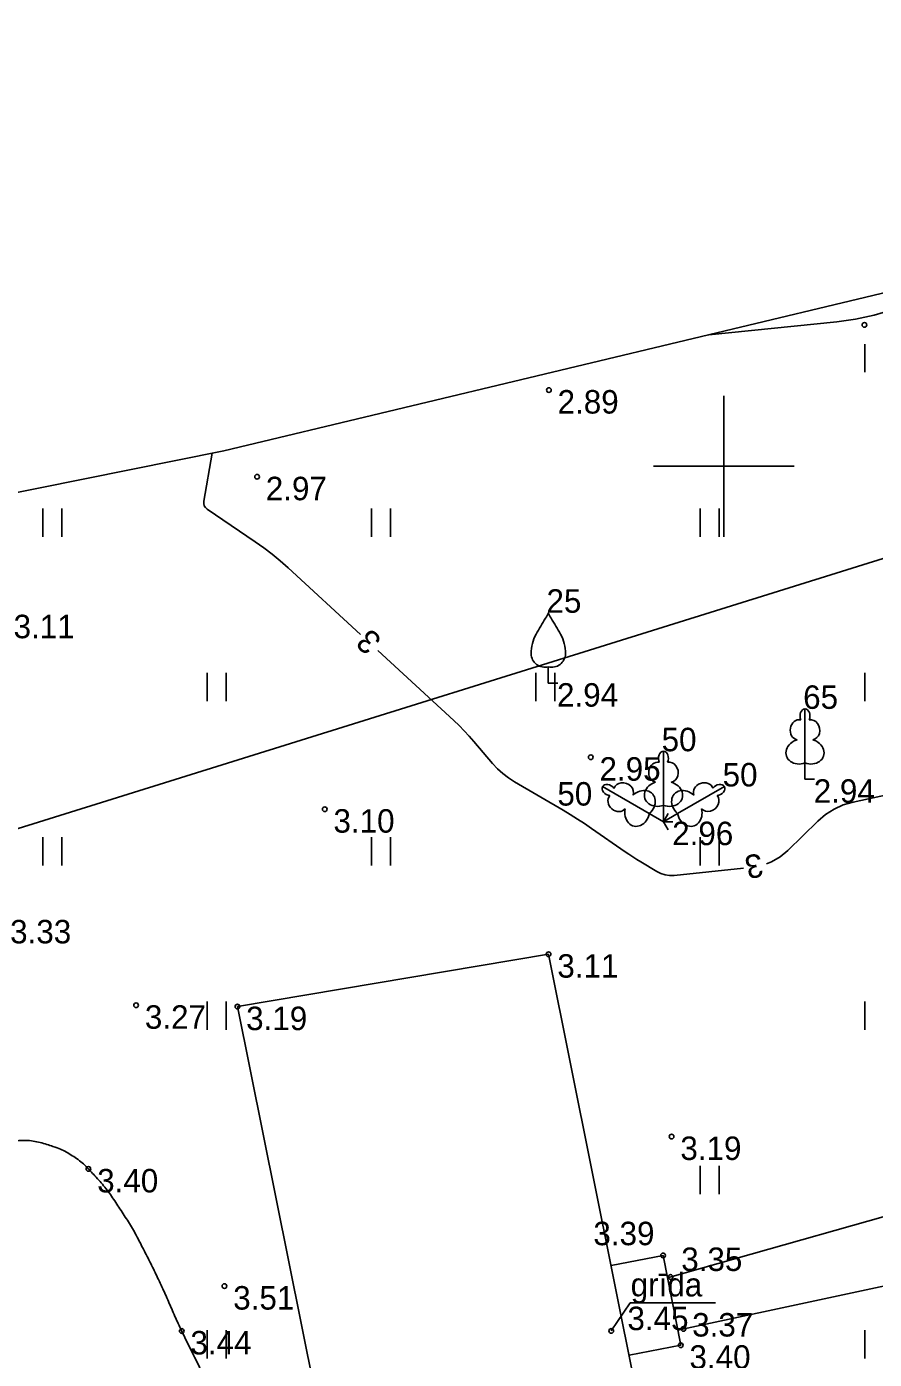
# Model space of a CAD drawing. Extents: x 321079 to 321220, y 257030 to 257220.
# Drawn here: x 321135.15 to 321153.21, y 257130.98 to 257159.36 of the extents above; entities that cross this region are included whole.
import ezdxf

# ---------------------------------------------------------------- set-up
doc = ezdxf.new("R2010")
doc.units = 0
for name, color, linetype in [('BUVE_BDET_####_####_#', 7, 'Continuous'), ('BUVE_BDET_####_TKST_#', 7, 'Continuous'), ('BUVE_EKAS_####_####_#', 7, 'Continuous'), ('CELI_CMAL_####_####_#', 7, 'Continuous'), ('GEOD_ELEM_####_####_#', 7, 'Continuous'), ('RAMI_UZMR_####_####_#', 7, 'Continuous'), ('RELJ_AATZ_####_TKST_#', 7, 'Continuous'), ('RELJ_ELEM_####_####_#', 7, 'Continuous'), ('RELJ_HORZ_####_TKST_#', 7, 'Continuous'), ('RELJ_HORZ_PAMT_####_#', 7, 'Continuous'), ('RELJ_HORZ_PUSH_####_#', 7, 'Continuous'), ('ROBZ_UZMR_####_####_#', 7, 'Continuous'), ('TERT_DIAM_####_TKST_#', 7, 'Continuous'), ('TERT_ELEM_####_####_#', 7, 'Continuous'), ('TERT_KONT_####_####_#', 7, 'Continuous')]:
    doc.layers.add(name, color=color, linetype=linetype)

msp = doc.modelspace()

# ---------------------------------------------------------------- linework, layer by layer
at = {"layer": 'BUVE_BDET_####_####_#'}
for points in [[(321147.601, 257132.975), (321148.708, 257133.192), (321149.083, 257131.28), (321147.985, 257131.065)], [(321147.604, 257131.586), (321148.008, 257132.186), (321149.825, 257132.186)]]:
    msp.add_lwpolyline(points, dxfattribs=at)
at = {"layer": 'BUVE_EKAS_####_####_#'}
for p, q in [((321146.269, 257139.608), (321139.642, 257138.491)), ((321150.164, 257120.215), (321146.269, 257139.608)), ((321139.642, 257138.491), (321143.539, 257119.128))]:
    msp.add_line(p, q, dxfattribs=at)
at = {"layer": 'CELI_CMAL_####_####_#'}
msp.add_lwpolyline([(321149.02, 257131.603), (321155.747, 257133.045), (321162.788, 257134.403), (321162.477, 257135.836), (321155.228, 257134.532), (321148.802, 257132.714)], dxfattribs=at)
at = {"layer": 'GEOD_ELEM_####_####_#'}
for p, q in [((321150, 257151.5), (321150, 257150)), ((321148.5, 257150), (321150, 257150)), ((321150, 257150), (321150, 257148.5)), ((321150, 257150), (321151.5, 257150))]:
    msp.add_line(p, q, dxfattribs=at)
at = {"layer": 'RAMI_UZMR_####_####_#'}
msp.add_lwpolyline([(321107.5, 257141.5), (321108.611, 257133.395), (321131.584, 257099.382), (321150.327, 257105.322), (321177.121, 257109.842), (321183.308, 257111.386), (321177.517, 257137.442), (321172.561, 257161.05), (321156.27, 257158.872), (321156.852, 257154.517), (321139.352, 257150.329), (321114.57, 257145.337)], close=True, dxfattribs=at)
at = {"layer": 'RELJ_ELEM_####_####_#'}
for centre in [(321152.996, 257153.01), (321146.275, 257151.622), (321140.061, 257149.776), (321147.167, 257143.803), (321141.502, 257142.696), (321146.269, 257139.608), (321137.486, 257138.52), (321139.642, 257138.491), (321148.889, 257135.725), (321136.47, 257135.034), (321148.708, 257133.192), (321148.868, 257132.733), (321139.367, 257132.539), (321147.604, 257131.586), (321149.141, 257131.629), (321138.456, 257131.583), (321149.083, 257131.28)]:
    msp.add_circle(centre, 0.05, dxfattribs=at)
at = {"layer": 'RELJ_HORZ_PAMT_####_#'}
for points in [[(321139.108, 257150.28), (321138.929, 257149.254), (321138.926, 257149.203), (321138.937, 257149.158), (321138.962, 257149.118), (321139.001, 257149.085), (321140.023, 257148.393), (321140.205, 257148.264), (321140.383, 257148.129), (321140.555, 257147.987), (321140.723, 257147.838), (321142.264, 257146.416)], [(321142.632, 257146.077), (321144.251, 257144.583), (321144.363, 257144.477), (321144.471, 257144.367), (321144.576, 257144.254), (321144.678, 257144.139), (321145.078, 257143.669), (321145.183, 257143.556), (321145.295, 257143.454), (321145.416, 257143.361), (321145.545, 257143.278), (321146.578, 257142.673), (321146.731, 257142.581), (321146.883, 257142.486), (321147.033, 257142.389), (321147.18, 257142.288), (321147.899, 257141.791), (321147.981, 257141.735), (321148.064, 257141.68), (321148.148, 257141.626), (321148.233, 257141.574), (321148.575, 257141.367), (321148.662, 257141.323), (321148.752, 257141.295), (321148.846, 257141.282), (321148.944, 257141.285), (321150.418, 257141.441)], [(321150.909, 257141.534), (321151.016, 257141.573), (321151.199, 257141.679), (321151.365, 257141.818), (321152.001, 257142.441), (321152.167, 257142.583), (321152.348, 257142.698), (321152.543, 257142.786), (321152.753, 257142.847), (321154.846, 257143.299), (321155.268, 257143.383), (321155.693, 257143.454), (321156.119, 257143.511), (321156.548, 257143.554), (321159.404, 257143.796), (321159.478, 257143.809), (321159.545, 257143.836), (321159.604, 257143.877), (321159.656, 257143.932), (321159.732, 257144.027)]]:
    msp.add_lwpolyline(points, dxfattribs=at)
at = {"layer": 'RELJ_HORZ_PUSH_####_#'}
msp.add_lwpolyline([(321149.681, 257152.801), (321152.406, 257153.078), (321152.806, 257153.133), (321153.2, 257153.217), (321153.586, 257153.328), (321153.965, 257153.468), (321155.798, 257154.217), (321156.01, 257154.284), (321156.223, 257154.313), (321156.438, 257154.303), (321156.654, 257154.254), (321157.523, 257153.982), (321157.524, 257153.982)], dxfattribs=at)
at = {"layer": 'ROBZ_UZMR_####_####_#'}
msp.add_line((321109.842, 257134.432), (321160.832, 257150.36), dxfattribs=at)
at = {"layer": 'TERT_ELEM_####_####_#'}
for p, q in [((321153, 257152), (321153, 257152.6)), ((321135.5, 257148.5), (321135.5, 257149.1)), ((321135.9, 257148.5), (321135.9, 257149.1)), ((321142.5, 257148.5), (321142.5, 257149.1)), ((321142.9, 257148.5), (321142.9, 257149.1)), ((321149.5, 257148.5), (321149.5, 257149.1)), ((321149.9, 257148.5), (321149.9, 257149.1)), ((321139, 257145), (321139, 257145.6)), ((321139.4, 257145), (321139.4, 257145.6)), ((321146, 257145), (321146, 257145.6)), ((321146.263, 257145.732), (321146.263, 257145.38)), ((321146.4, 257145), (321146.4, 257145.6)), ((321153, 257145), (321153, 257145.6)), ((321146.263, 257145.38), (321146.463, 257145.38)), ((321151.729, 257143.68), (321151.729, 257143.333)), ((321151.729, 257143.333), (321151.929, 257143.333)), ((321148.715, 257142.777), (321148.715, 257142.43)), ((321148.414, 257142.603), (321148.715, 257142.43)), ((321148.715, 257142.43), (321148.815, 257142.603)), ((321149.016, 257142.603), (321148.715, 257142.43)), ((321148.715, 257142.43), (321148.915, 257142.43)), ((321148.715, 257142.43), (321148.815, 257142.257)), ((321135.5, 257141.5), (321135.5, 257142.1)), ((321135.9, 257141.5), (321135.9, 257142.1)), ((321142.5, 257141.5), (321142.5, 257142.1)), ((321142.9, 257141.5), (321142.9, 257142.1)), ((321149.5, 257141.5), (321149.5, 257142.1)), ((321149.9, 257141.5), (321149.9, 257142.1)), ((321139, 257138), (321139, 257138.6)), ((321139.4, 257138), (321139.4, 257138.6)), ((321153, 257138), (321153, 257138.6)), ((321149.5, 257134.5), (321149.5, 257135.1)), ((321149.9, 257134.5), (321149.9, 257135.1)), ((321139, 257131), (321139, 257131.6)), ((321139.4, 257131), (321139.4, 257131.6)), ((321153, 257131), (321153, 257131.6))]:
    msp.add_line(p, q, dxfattribs=at)
for points in [[(321151.729, 257144.833), (321151.729, 257143.68)], [(321151.819, 257144.601), (321151.818, 257144.602)], [(321148.715, 257143.93), (321148.715, 257142.777)], [(321148.805, 257143.698), (321148.804, 257143.699)], [(321147.416, 257143.18), (321148.414, 257142.603)], [(321147.662, 257143.141), (321147.661, 257143.141)], [(321150.014, 257143.18), (321149.016, 257142.603)], [(321149.858, 257142.986), (321149.858, 257142.988)]]:
    msp.add_lwpolyline(points, dxfattribs=at)
for centre, radius, start, end in [((321158.888, 257138.984), 14.88, 148.4844, 149.9901), ((321145.846, 257147.018), 0.439, 324.3837, 341.712), ((321146.68, 257147.018), 0.439, 198.288, 215.6163), ((321133.638, 257138.984), 14.88, 30.0099, 31.5156), ((321146.787, 257146.005), 0.89, 151.757, 179.9138), ((321145.739, 257146.005), 0.89, 0.0862, 28.243), ((321146.187, 257146.011), 0.29, 181.0782, 285.2823), ((321146.339, 257146.011), 0.29, 254.7177, 358.9218)]:
    msp.add_arc(centre, radius, start, end, dxfattribs=at)
for centre, major_axis, ratio, start_param, end_param in [((321151.729, 257144.683), (0, -0.15), 0.707107, 3.14537, 5.287485), ((321151.729, 257144.683), (0, -0.15), 0.707107, 0.995701, 3.137816), ((321151.601, 257144.388), (-0.039, -0.212), 0.861323, 3.141593, 6.283185), ((321151.857, 257144.388), (0.039, -0.212), 0.861323, 0, 3.141593), ((321151.639, 257143.926), (0.307, 0.095), 0.814445, 1.570796, 4.752015), ((321151.819, 257143.926), (-0.307, 0.095), 0.814445, 1.531171, 4.712389), ((321148.715, 257143.78), (0, -0.15), 0.707107, 3.14537, 5.287485), ((321148.715, 257143.78), (0, -0.15), 0.707107, 0.995701, 3.137816), ((321148.587, 257143.485), (-0.039, -0.212), 0.861323, 3.141593, 6.283185), ((321148.843, 257143.485), (0.039, -0.212), 0.861323, 0, 3.141593), ((321147.865, 257143.069), (0.203, -0.073), 0.861323, 0, 3.141593), ((321148.625, 257143.023), (0.307, 0.095), 0.814445, 1.570796, 4.752015), ((321148.805, 257143.023), (-0.307, 0.095), 0.814445, 1.531171, 4.712389), ((321149.565, 257143.069), (-0.203, -0.073), 0.861323, 3.141593, 6.283185), ((321147.546, 257143.105), (0.13, -0.075), 0.707107, 3.14537, 5.287485), ((321147.546, 257143.105), (0.13, -0.075), 0.707107, 0.995701, 3.137816), ((321148.246, 257142.804), (-0.236, -0.218), 0.814445, 1.531171, 4.712389), ((321149.184, 257142.804), (0.236, -0.218), 0.814445, 1.570796, 4.752015), ((321149.884, 257143.105), (-0.13, -0.075), 0.707107, 3.14537, 5.287485), ((321149.884, 257143.105), (-0.13, -0.075), 0.707107, 0.995701, 3.137816), ((321147.737, 257142.846), (0.165, -0.14), 0.861323, 3.141593, 6.283185), ((321148.157, 257142.649), (0.071, 0.313), 0.814445, 1.570796, 4.752015), ((321149.273, 257142.649), (-0.071, 0.313), 0.814445, 1.531171, 4.712389), ((321149.693, 257142.846), (-0.165, -0.14), 0.861323, 0, 3.141593)]:
    msp.add_ellipse(centre, major_axis=major_axis, ratio=ratio, start_param=start_param, end_param=end_param, dxfattribs=at)
at = {"layer": 'TERT_KONT_####_####_#'}
msp.add_open_spline([(321129.296, 257148.304), (321129.341, 257148.261), (321129.386, 257148.219), (321129.431, 257148.175), (321129.997, 257147.629), (321130.535, 257147.084), (321131.007, 257146.464), (321131.229, 257146.173), (321131.445, 257145.88), (321131.641, 257145.571), (321131.732, 257145.427), (321131.822, 257145.282), (321131.907, 257145.134), (321131.947, 257145.064), (321131.986, 257144.992), (321132.026, 257144.921), (321132.063, 257144.852), (321132.099, 257144.783), (321132.134, 257144.712), (321132.197, 257144.587), (321132.235, 257144.453), (321132.271, 257144.317), (321132.304, 257144.188), (321132.307, 257144.052), (321132.294, 257143.922), (321132.267, 257143.648), (321132.204, 257143.378), (321132.049, 257143.129), (321131.664, 257142.512), (321131.238, 257142.013), (321130.74, 257141.535), (321130.167, 257140.985), (321129.559, 257140.48), (321128.996, 257139.924), (321128.727, 257139.659), (321128.461, 257139.391), (321128.207, 257139.11), (321128.089, 257138.98), (321127.978, 257138.844), (321127.876, 257138.701), (321127.78, 257138.567), (321127.689, 257138.431), (321127.604, 257138.29), (321127.372, 257137.904), (321127.146, 257137.516), (321126.921, 257137.126), (321126.204, 257135.885), (321125.508, 257134.637), (321124.83, 257133.371), (321124.395, 257132.558), (321124.066, 257131.698), (321123.781, 257130.816), (321123.649, 257130.407), (321123.546, 257129.995), (321123.474, 257129.573), (321123.44, 257129.372), (321123.41, 257129.171), (321123.392, 257128.968), (321123.382, 257128.868), (321123.376, 257128.769), (321123.37, 257128.67), (321123.364, 257128.572), (321123.362, 257128.474), (321123.363, 257128.376), (321123.363, 257128.279), (321123.397, 257128.188), (321123.453, 257128.099), (321123.517, 257127.997), (321123.596, 257127.929), (321123.697, 257127.871), (321123.95, 257127.726), (321124.201, 257127.63), (321124.477, 257127.566), (321124.773, 257127.498), (321125.07, 257127.468), (321125.365, 257127.469), (321125.586, 257127.469), (321125.807, 257127.489), (321126.024, 257127.585), (321126.11, 257127.623), (321126.176, 257127.675), (321126.244, 257127.735), (321126.317, 257127.8), (321126.385, 257127.864), (321126.446, 257127.94), (321126.585, 257128.113), (321126.721, 257128.288), (321126.81, 257128.488), (321127.025, 257128.97), (321127.24, 257129.453), (321127.454, 257129.935), (321127.682, 257130.449), (321127.909, 257130.964), (321128.138, 257131.479), (321128.244, 257131.718), (321128.394, 257131.934), (321128.552, 257132.146), (321128.662, 257132.293), (321128.779, 257132.43), (321128.913, 257132.555), (321128.956, 257132.595), (321128.999, 257132.633), (321129.045, 257132.669), (321129.307, 257132.877), (321129.57, 257133.08), (321129.838, 257133.28), (321130.141, 257133.505), (321130.45, 257133.717), (321130.763, 257133.93), (321131.417, 257134.374), (321132.085, 257134.734), (321132.823, 257135.088), (321133.478, 257135.403), (321134.165, 257135.57), (321134.85, 257135.629), (321135.141, 257135.654), (321135.444, 257135.606), (321135.734, 257135.506), (321135.875, 257135.457), (321136.001, 257135.399), (321136.124, 257135.317), (321136.251, 257135.233), (321136.366, 257135.144), (321136.47, 257135.034), (321136.693, 257134.798), (321136.896, 257134.556), (321137.073, 257134.288), (321137.256, 257134.01), (321137.432, 257133.732), (321137.583, 257133.438), (321137.739, 257133.135), (321137.891, 257132.832), (321138.033, 257132.524), (321138.177, 257132.212), (321138.309, 257131.894), (321138.456, 257131.583), (321138.59, 257131.301), (321138.733, 257131.023), (321138.869, 257130.742), (321139.009, 257130.456), (321139.139, 257130.17), (321139.267, 257129.874), (321139.384, 257129.605), (321139.444, 257129.316), (321139.472, 257129.03), (321139.485, 257128.899), (321139.474, 257128.764), (321139.446, 257128.633), (321139.433, 257128.568), (321139.415, 257128.506), (321139.391, 257128.443), (321139.367, 257128.38), (321139.34, 257128.32), (321139.305, 257128.261), (321139.147, 257127.999), (321138.966, 257127.764), (321138.743, 257127.556), (321138.511, 257127.34), (321138.274, 257127.139), (321138.012, 257126.967), (321137.742, 257126.789), (321137.472, 257126.612), (321137.197, 257126.441), (321137.059, 257126.356), (321136.921, 257126.272), (321136.784, 257126.186), (321136.648, 257126.102), (321136.516, 257126.013), (321136.381, 257125.928), (321136.104, 257125.753), (321135.818, 257125.594), (321135.521, 257125.454), (321135.219, 257125.311), (321134.907, 257125.196), (321134.594, 257125.083), (321133.961, 257124.856), (321133.312, 257124.683), (321132.677, 257124.46), (321132.063, 257124.245), (321131.471, 257123.99), (321130.897, 257123.67), (321130.617, 257123.514), (321130.371, 257123.316), (321130.143, 257123.092), (321130.026, 257122.978), (321129.916, 257122.862), (321129.814, 257122.736), (321129.763, 257122.671), (321129.713, 257122.606), (321129.664, 257122.538), (321129.615, 257122.47), (321129.568, 257122.4), (321129.524, 257122.327), (321129.259, 257121.895), (321129.047, 257121.444), (321128.858, 257120.971), (321128.674, 257120.511), (321128.527, 257120.045), (321128.449, 257119.559), (321128.293, 257118.586), (321128.187, 257117.612), (321128.124, 257116.631), (321128.06, 257115.644), (321128.061, 257114.653), (321127.991, 257113.666), (321127.956, 257113.177), (321127.906, 257112.691), (321127.823, 257112.207), (321127.74, 257111.725), (321127.638, 257111.249), (321127.494, 257110.784), (321127.116, 257109.561), (321126.739, 257108.338), (321126.361, 257107.115)], degree=3, dxfattribs=at)

# ---------------------------------------------------------------- texts
at = {"layer": 'BUVE_BDET_####_TKST_#'}
for s, p in [('grīda', (321148.017, 257132.319)), (' 3.45', (321147.762, 257131.601))]:
    msp.add_text(s, height=0.5, dxfattribs=at).set_placement(p)
at = {"layer": 'RELJ_AATZ_####_TKST_#'}
for s, p in [(' 2.89', (321146.275, 257151.122)), (' 2.97', (321140.061, 257149.276)), (' 3.11', (321134.69, 257146.337)), (' 2.94', (321146.263, 257144.88)), (' 2.95', (321147.167, 257143.303)), (' 2.94', (321151.729, 257142.833)), (' 3.10', (321141.502, 257142.196)), (' 2.96', (321148.715, 257141.93)), (' 3.33', (321134.616, 257139.838)), (' 3.11', (321146.269, 257139.108)), (' 3.27', (321137.486, 257138.02)), (' 3.19', (321139.642, 257137.991)), (' 3.19', (321148.889, 257135.225)), (' 3.40', (321136.47, 257134.534)), (' 3.39', (321147.037, 257133.41)), (' 3.35', (321148.908, 257132.861)), (' 3.51', (321139.367, 257132.039)), (' 3.37', (321149.141, 257131.465)), (' 3.44', (321138.456, 257131.083)), (' 3.40', (321149.083, 257130.78))]:
    msp.add_text(s, height=0.5, dxfattribs=at).set_placement(p)
at = {"layer": 'RELJ_HORZ_####_TKST_#'}
for rotation, p in [(137.3002, (321142.741, 257146.316)), (190.7381, (321150.782, 257141.764))]:
    msp.add_text('3', height=0.5, rotation=rotation, dxfattribs=at).set_placement(p)
at = {"layer": 'TERT_DIAM_####_TKST_#'}
for s, p in [(' 25', (321146.038, 257146.88)), (' 65', (321151.504, 257144.833)), (' 50', (321148.49, 257143.93)), (' 50', (321149.789, 257143.18)), (' 50', (321146.27, 257142.773))]:
    msp.add_text(s, height=0.5, dxfattribs=at).set_placement(p)

doc.saveas('drawing.dxf')
